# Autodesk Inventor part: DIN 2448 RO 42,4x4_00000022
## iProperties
Created: 2006-02
Part Number: DIN 2448 RO 42,4x4_00000022
Material: Default
Document SubType Name: Modeling
Designer: FranzK
Stock Number: DIN 2448 RO 42,4x4
Mass: 438.333 g
Surface Area: 2198.88 cm^2
Volume: 438.333 cm^3
Density: 1 g/cm^3
G_L: 894.000 mm
G_W: 42.400 mm
G_H: 42.400 mm
AFG_Item: 42.4 x 4
CSToolsMass: 0.4
CSToolsVolume: 438333.0
CSToolsArea: 2199.0
Author: FranzK
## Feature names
1. AFG_Detailed_DIN 2448 RO 42,4x4_00000022 [Extrusion]
2. AFG_Simplified_DIN 2448 RO 42,4x4_00000022 [Extrusion]
3. Extrusion5
